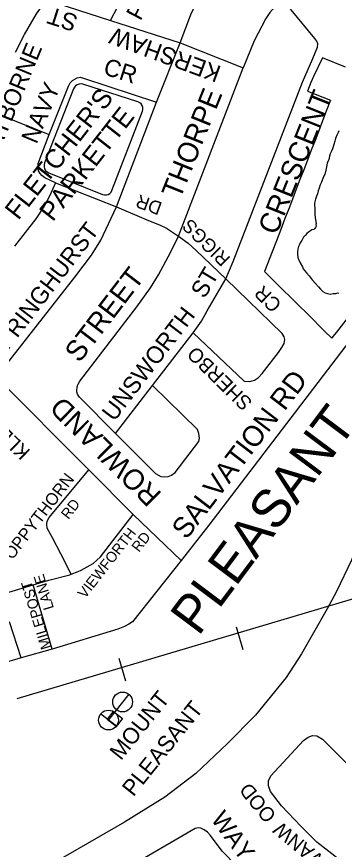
# Model space of a CAD drawing. Extents: x 586326 to 623965, y 4819854 to 4857850.
# Drawn here: x 595018 to 595356, y 4836331 to 4837207 of the extents above; entities that cross this region are included whole.
import ezdxf

# ---------------------------------------------------------------- set-up
doc = ezdxf.new("R2010")
doc.units = 0
for name, color, linetype in [('GO Stations', 7, 'Continuous'), ('Major Rds and Hwys', 7, 'Continuous'), ('Minor Rd Lbls', 7, 'Continuous'), ('Minor Rds', 7, 'Continuous'), ('Park Lbls', 7, 'Continuous'), ('Park Outlines', 7, 'Continuous'), ('Proposed Secondary Rds', 7, 'Continuous'), ('Pts of Interest', 7, 'Continuous'), ('Railways_lbls', 7, 'Continuous'), ('Secondary Rds Lbls', 7, 'Continuous'), ('SWM Ponds', 7, 'Continuous')]:
    doc.layers.add(name, color=color, linetype=linetype)

msp = doc.modelspace()

# ---------------------------------------------------------------- linework, layer by layer
at = {"layer": 'GO Stations'}
for p, q in [((595135.59, 4836494.05), (595114.47, 4836467.03)), ((595106.25, 4836473.44), (595122.63, 4836460.65))]:
    msp.add_line(p, q, dxfattribs=at)
msp.add_lwpolyline([(595119.65, 4836475.84), (595128.88, 4836468.63), (595122.22, 4836460.11), (595112.97, 4836467.34)], close=True, dxfattribs=at)
for centre in [(595129.15, 4836485.89), (595114.31, 4836466.89)]:
    msp.add_circle(centre, 10.4, dxfattribs=at)
at = {"layer": 'Major Rds and Hwys'}
for points in [[(595537.32, 4837074.96), (595508.03, 4837030.94), (595482.16, 4836981.47), (595459.78, 4836933.73), (595445.14, 4836889.38), (595431.71, 4836843.47), (595419.12, 4836796.3), (595400.24, 4836730.99), (595381.15, 4836664.64), (595369.81, 4836634.99), (595354.27, 4836602.03), (595344.33, 4836583.96)], [(595344.33, 4836583.96), (595329.75, 4836558.47), (595317.24, 4836536.69), (595300.99, 4836511.69), (595268.81, 4836472.09), (595239.61, 4836442.05), (595206.18, 4836410.8), (595173.59, 4836385.87), (595131.28, 4836359.51), (594933.6, 4836245.89)]]:
    msp.add_lwpolyline(points, dxfattribs=at)
at = {"layer": 'Minor Rds'}
for points in [[(595116.48, 4837202.64), (595151.46, 4837270.2), (595157.19, 4837276.96), (595186.27, 4837315.13), (595190.56, 4837323.61), (595189.43, 4837331), (595186.78, 4837334.98), (595182.22, 4837340.46), (595151.55, 4837370.18)], [(595016.49, 4837169.41), (595025.83, 4837187.99), (595038.67, 4837209.64), (595048.96, 4837224.81)], [(595048.96, 4837224.81), (595116.48, 4837202.64)], [(595237.73, 4836931), (595245.55, 4836949.39), (595318.2, 4837137.94), (595329.37, 4837162.92), (595334.16, 4837174.69), (595334.61, 4837178.14), (595333.54, 4837180.99), (595331.21, 4837183.97), (595306.35, 4837213.98), (595303.16, 4837216.63), (595299.45, 4837217.82), (595295.15, 4837218.25), (595290.79, 4837217.02), (595286.96, 4837214.29), (595283.87, 4837211.14), (595279.85, 4837205), (595267.38, 4837181.52), (595255.88, 4837152.88)], [(595116.48, 4837202.64), (595189.58, 4837179.19)], [(595189.58, 4837179.19), (595255.88, 4837152.88)], [(595187.77, 4836975.8), (595255.88, 4837152.88)], [(595442.14, 4837151.85), (595424.96, 4837133.76), (595421.31, 4837127.7), (595419.98, 4837123.27), (595418.99, 4837117.77), (595419.46, 4837111.97), (595420.94, 4837106.91), (595425.38, 4837099.52), (595433.16, 4837090.84), (595458.52, 4837065.15), (595463.73, 4837056.52), (595465.81, 4837050.55), (595466.98, 4837043.49), (595467.46, 4837037.08), (595466.27, 4837028.88), (595462.78, 4837020.52), (595451.52, 4836999.98), (595425.34, 4836954.79), (595413.77, 4836934.7), (595396.18, 4836906.81), (595381.36, 4836884.59), (595368.33, 4836866.52), (595219.78, 4836671.9), (595190.87, 4836634.67)], [(595051.79, 4837082.78), (595072.4, 4837133.81), (595074.08, 4837137.09), (595076.47, 4837139.47), (595079.04, 4837141.17), (595081.26, 4837142.44), (595084.56, 4837143.04), (595087.94, 4837142.17), (595164.65, 4837116.87)], [(594990.88, 4837106.92), (595051.79, 4837082.78)], [(595058.47, 4837031.98), (595047.25, 4837037.38), (595044.25, 4837039.64), (595042.43, 4837041.85), (595040.79, 4837044.73), (595039.82, 4837047.78), (595040.24, 4837052.4), (595051.79, 4837082.78)], [(595058.47, 4837031.98), (595052.27, 4837018.12), (595046.52, 4837007.43), (595037.97, 4836994.11), (595015.47, 4836965.27)], [(595058.47, 4837031.98), (595122.71, 4837006.74)], [(595122.71, 4837006.74), (595156.32, 4836992.37), (595167.8, 4836987.65), (595175.25, 4836984.17), (595187.77, 4836975.8)], [(595121.59, 4836768.46), (595083.73, 4836806.39), (595081.77, 4836809.66), (595081.12, 4836812.12), (595081.14, 4836814.37), (595081.28, 4836816.51), (595081.76, 4836818.7), (595082.31, 4836820.33), (595084.05, 4836823.48), (595144.25, 4836901.39), (595158.57, 4836921.47), (595166.83, 4836935.07), (595179.4, 4836958.56), (595187.77, 4836975.8)], [(595187.77, 4836975.8), (595198.02, 4836968.47), (595206.6, 4836960.75), (595237.73, 4836931)], [(595203.26, 4836874.1), (595256.98, 4836823.43), (595263.07, 4836822.84), (595267.89, 4836824.44), (595272.08, 4836827.13), (595275.92, 4836831.28), (595293.09, 4836853.63), (595296.62, 4836858.92), (595299.14, 4836862.91), (595299.6, 4836867.32), (595299.1, 4836870.1), (595297, 4836873.52), (595237.73, 4836931)], [(595203.26, 4836874.1), (595212.25, 4836886.59), (595218.22, 4836897.46), (595237.73, 4836931)], [(595160.7, 4836818.89), (595203.26, 4836874.1)], [(595093.68, 4836730.21), (594996.01, 4836827.63)], [(595121.59, 4836768.46), (595160.7, 4836818.89)], [(595121.59, 4836768.46), (595163.83, 4836726.34), (595169.45, 4836723.21), (595173.29, 4836722.87), (595176.95, 4836723.09), (595180.57, 4836724.57), (595184.38, 4836727.34), (595209.34, 4836759.91), (595210, 4836763.55), (595209.41, 4836768.32), (595207.88, 4836772.39), (595160.7, 4836818.89)], [(595064.1, 4836641.67), (595055.51, 4836658.47), (595049.81, 4836668.64), (595049.29, 4836672.89), (595049.74, 4836676.23), (595051.97, 4836679.86), (595093.68, 4836730.21)], [(595140.27, 4836683.25), (595093.68, 4836730.21)], [(595082.57, 4836623.19), (595085.69, 4836624.4), (595098.35, 4836631.56), (595105.83, 4836638.48), (595140.27, 4836683.25)], [(595190.87, 4836634.67), (595140.27, 4836683.25)], [(595075.05, 4836620.26), (595064.1, 4836641.67)], [(595190.87, 4836634.67), (595139.47, 4836570.37), (595135.77, 4836567.67)], [(595035.14, 4836609.22), (595051.44, 4836613.9), (595073.5, 4836619.71), (595075.05, 4836620.26)], [(595075.05, 4836620.26), (595082.57, 4836623.19)], [(595001.26, 4836599.07), (595035.14, 4836609.22)], [(595054.98, 4836541.4), (595035.14, 4836609.22)], [(595022.55, 4836532.17), (595010.21, 4836570.07)], [(595135.77, 4836567.67), (595130.97, 4836565.29), (595124.12, 4836562.65), (595054.98, 4836541.4)], [(595054.98, 4836541.4), (595022.55, 4836532.17)], [(595022.55, 4836532.17), (594939.78, 4836507.71)], [(595366.43, 4836312.34), (595349.14, 4836326.05), (595333.49, 4836338.48), (595316.99, 4836355.03), (595296.24, 4836376.51), (595284.58, 4836391.71), (595282.61, 4836397.51), (595282.75, 4836402.88), (595285.06, 4836408.18), (595319.48, 4836445.21), (595324.38, 4836448.89), (595328.84, 4836450.47), (595333.55, 4836450.24), (595339.21, 4836446.84), (595378.3, 4836407.78)], [(595319.14, 4836251.44), (595280.1, 4836281.77), (595233.92, 4836328.93), (595221.74, 4836345.32), (595218.58, 4836348.8), (595214.85, 4836351.54), (595211.47, 4836353.01), (595208.89, 4836353.35), (595205.38, 4836352.73), (595148.17, 4836319.44)]]:
    msp.add_lwpolyline(points, dxfattribs=at)
at = {"layer": 'Park Outlines'}
msp.add_lwpolyline([(595363.68, 4837153.78), (595339.46, 4837163.42), (595329.98, 4837143.9), (595328.45, 4837140.55), (595327.17, 4837137.41), (595323.66, 4837128.28), (595347.82, 4837118.98), (595343.34, 4837107.32), (595339.39, 4837097.06), (595335.44, 4837086.79), (595331.49, 4837076.53), (595327.54, 4837066.27), (595323.59, 4837056), (595319.64, 4837045.74), (595315.69, 4837035.48), (595311.74, 4837025.21), (595307.8, 4837014.95), (595303.85, 4837004.69), (595299.9, 4836994.42), (595295.41, 4836982.76), (595290.92, 4836971.1), (595286.44, 4836959.43), (595278.42, 4836938.61), (595281.79, 4836935.28), (595289.71, 4836927.43), (595297.63, 4836919.59), (595305.56, 4836911.75), (595313.48, 4836903.91), (595324.15, 4836893.35), (595341.61, 4836876.07), (595349.27, 4836868.49), (595350.02, 4836869.44), (595350.64, 4836870.24), (595354.32, 4836874.97), (595407.24, 4836942.84)], dxfattribs=at)
msp.add_lwpolyline([(595077.41, 4837130.82), (595046.97, 4837053), (595046.47, 4837050.95), (595046.5, 4837048.83), (595047.08, 4837046.8), (595048.17, 4837044.99), (595049.68, 4837043.51), (595051.52, 4837042.47), (595108.14, 4837019.73), (595110.05, 4837019.24), (595112.03, 4837019.27), (595113.93, 4837019.81), (595115.62, 4837020.83), (595116.98, 4837022.26), (595117.93, 4837023.99), (595149.98, 4837107.29), (595150.45, 4837109.26), (595150.37, 4837111.29), (595149.74, 4837113.22), (595148.63, 4837114.92), (595147.1, 4837116.25), (595145.27, 4837117.12), (595087.48, 4837135.61), (595085.48, 4837135.99), (595083.44, 4837135.85), (595081.5, 4837135.21), (595079.74, 4837134.07), (595078.39, 4837132.62)], close=True, dxfattribs=at)
at = {"layer": 'Proposed Secondary Rds'}
for points in [[(595189.58, 4837179.19), (595201.7, 4837210.93), (595209.38, 4837226.23), (595216.95, 4837240.02), (595225.7, 4837253.95), (595233.56, 4837265.38), (595244.3, 4837277.75), (595259.24, 4837294.83), (595290.95, 4837327.72)], [(595164.65, 4837116.87), (595189.58, 4837179.19)], [(595122.71, 4837006.74), (595164.65, 4837116.87)], [(594996.01, 4836827.63), (595078.8, 4836932.69), (595096.42, 4836956.01), (595106.29, 4836971.8), (595122.71, 4837006.74)]]:
    msp.add_lwpolyline(points, dxfattribs=at)
at = {"layer": 'Railways_lbls'}
for p, q in [((595248.48, 4836565.1), (595255.48, 4836541.1)), ((595125.31, 4836532.06), (595132.31, 4836508.06))]:
    msp.add_line(p, q, dxfattribs=at)
msp.add_lwpolyline([(595921.93, 4836756.32), (595564.93, 4836652.32), (595562.93, 4836651.32), (595017.93, 4836489.32)], dxfattribs=at)
at = {"layer": 'SWM Ponds'}
msp.add_lwpolyline([(595356.62, 4837086.63), (595355.73, 4837084.98), (595354.44, 4837082.03), (595353.22, 4837078.51), (595352.4, 4837075.9), (595351.2, 4837072.16), (595349.87, 4837067.72), (595348.76, 4837065.13), (595347.33, 4837062.38), (595346.72, 4837059.91), (595345.99, 4837056.51), (595344.3, 4837052.66), (595343.55, 4837048.97), (595342.93, 4837045.19), (595341.76, 4837040.82), (595340.06, 4837037.47), (595338.19, 4837032.74), (595336.95, 4837029.85), (595335.85, 4837026.23), (595334.7, 4837023.47), (595334.05, 4837020.42), (595333.11, 4837017.91), (595332.13, 4837014.71), (595330.96, 4837010.74), (595330.9, 4837008.45), (595331.22, 4837005.35), (595331.36, 4837001.89), (595331.36, 4836998.64), (595331.5, 4836995.69), (595332, 4836992.95), (595332.57, 4836989.26), (595332.37, 4836988.09), (595332.57, 4836986.52), (595332.17, 4836985.1), (595331.41, 4836983.87), (595330.14, 4836983.03), (595328.16, 4836982.44), (595326.86, 4836981.43), (595324.8, 4836980.09), (595323.04, 4836978.62), (595321.06, 4836976.61), (595319.34, 4836974.8), (595318.23, 4836972.72), (595317.61, 4836971.28), (595316.75, 4836969.92), (595315.85, 4836968.89), (595315.09, 4836967.15), (595314.17, 4836964.92), (595313.36, 4836962.2), (595312.92, 4836959.29), (595313.15, 4836956.47), (595313.3, 4836954.32), (595313.44, 4836953.19), (595314.18, 4836951.8), (595315.79, 4836948.01), (595318.25, 4836943.74), (595319.21, 4836941.47), (595322.39, 4836937.46), (595325.2, 4836934.04), (595328.6, 4836930.07), (595332.06, 4836926.04), (595335, 4836922.52), (595337.28, 4836920.24), (595339.78, 4836917.58), (595342.22, 4836916.28), (595344.72, 4836915.44), (595347.57, 4836914.94), (595350.69, 4836915.55), (595352.44, 4836915.71), (595353.42, 4836915.66), (595354.32, 4836915.77), (595355.3, 4836916.12), (595356.29, 4836915.95)], dxfattribs=at)

# ---------------------------------------------------------------- texts
at = {"layer": 'GO Stations'}
for s, p in [('MOUNT ', (595127.41, 4836423.55)), ('PLEASANT', (595140.46, 4836385.48))]:
    msp.add_text(s, height=16.998, rotation=51.28938, dxfattribs=at).set_placement(p)
at = {"layer": 'Minor Rd Lbls'}
for s, height, rotation, p in [('PENN', 18, 62.44463, (595148.01, 4837201.64)), ('ST', 18, 161.84274, (595083.33, 4837207.73)), ('KERSHAW', 18, 159.83435, (595233.98, 4837154.17)), ('CLAYBORNE', 18, 67.41952, (594987.96, 4837037.09)), ('CR', 18, 342.45472, (595107.71, 4837146.49)), ('NAVY', 18, 67.41952, (595038.56, 4837072.05)), ('THORPE', 21.6, 68.1164, (595189.56, 4837013.92)), ('CRESCENT', 21.6, 68.1164, (595290.97, 4836976.12)), ('DR', 14, 160.11343, (595171.75, 4837010.87)), ('RIGGS', 14, 135.45372, (595243.38, 4836952.88)), ('STREET', 21.6, 52.52192, (595083.73, 4836841.78)), ('ST', 18, 59.07345, (595215.21, 4836909.31)), ('CR', 15, 135.55829, (595297.4, 4836904.92)), ('UNSWORTH', 18, 52.55743, (595120.26, 4836780.02)), ('KLEMSCOTT RD', 15, 135.49728, (595032.98, 4836749.93)), ('SHERBO', 15, 135.55829, (595266.57, 4836801.72)), ('SALVATION RD', 21.6, 52.6807, (595196.3, 4836655.86)), ('ROWLAND', 21.6, 135.45372, (595171.21, 4836705.12)), ('POPPYTHORN', 12.75, 52.39995, (595006.24, 4836625.75)), ('RD', 11, 52.39995, (595072.15, 4836677.31)), ('VIEWFORTH', 11, 52.00002, (595089.66, 4836593.98)), ('RD ', 11, 52.00002, (595146.3, 4836642.71)), ('LANE', 11, 106.82716, (595056.99, 4836584.61)), ('MILEPOST', 11, 106.82716, (595054.26, 4836543.06)), ('OOD', 15.088, 129.17479, (595291.53, 4836366.71)), ('WAY', 18.466, 306.04186, (595221.38, 4836362.56)), ('EVANW', 15.088, 140.22048, (595352.59, 4836313.49))]:
    msp.add_text(s, height=height, rotation=rotation, dxfattribs=at).set_placement(p)
at = {"layer": 'Park Lbls'}
for s, p in [("FLETCHER'S", (595019.43, 4836991.88)), ('PARKETTE', (595055.72, 4836990.24))]:
    msp.add_text(s, height=19.992, rotation=52.00002, dxfattribs=at).set_placement(p)
at = {"layer": 'Pts of Interest'}
msp.add_text('PLEASANT', height=39.984, rotation=53.17676, dxfattribs=at).set_placement((595208.87, 4836554.21))
at = {"layer": 'Secondary Rds Lbls'}
msp.add_text('SPRINGHURST', height=18, rotation=52.52192, dxfattribs=at).set_placement((594998.65, 4836842.42))

doc.saveas('drawing.dxf')
